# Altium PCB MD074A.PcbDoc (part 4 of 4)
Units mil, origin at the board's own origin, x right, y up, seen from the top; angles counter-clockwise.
Board outline 3224.41 x 4078.74 mil, 4 copper layers (Top Layer, Signal Layer 1, Signal Layer 2, Bottom Layer), stack 61.2 mil thick; 217 components, 121 nets, 624 pads, 901 vias.
Unrouted connection lines stored in the file: 116.
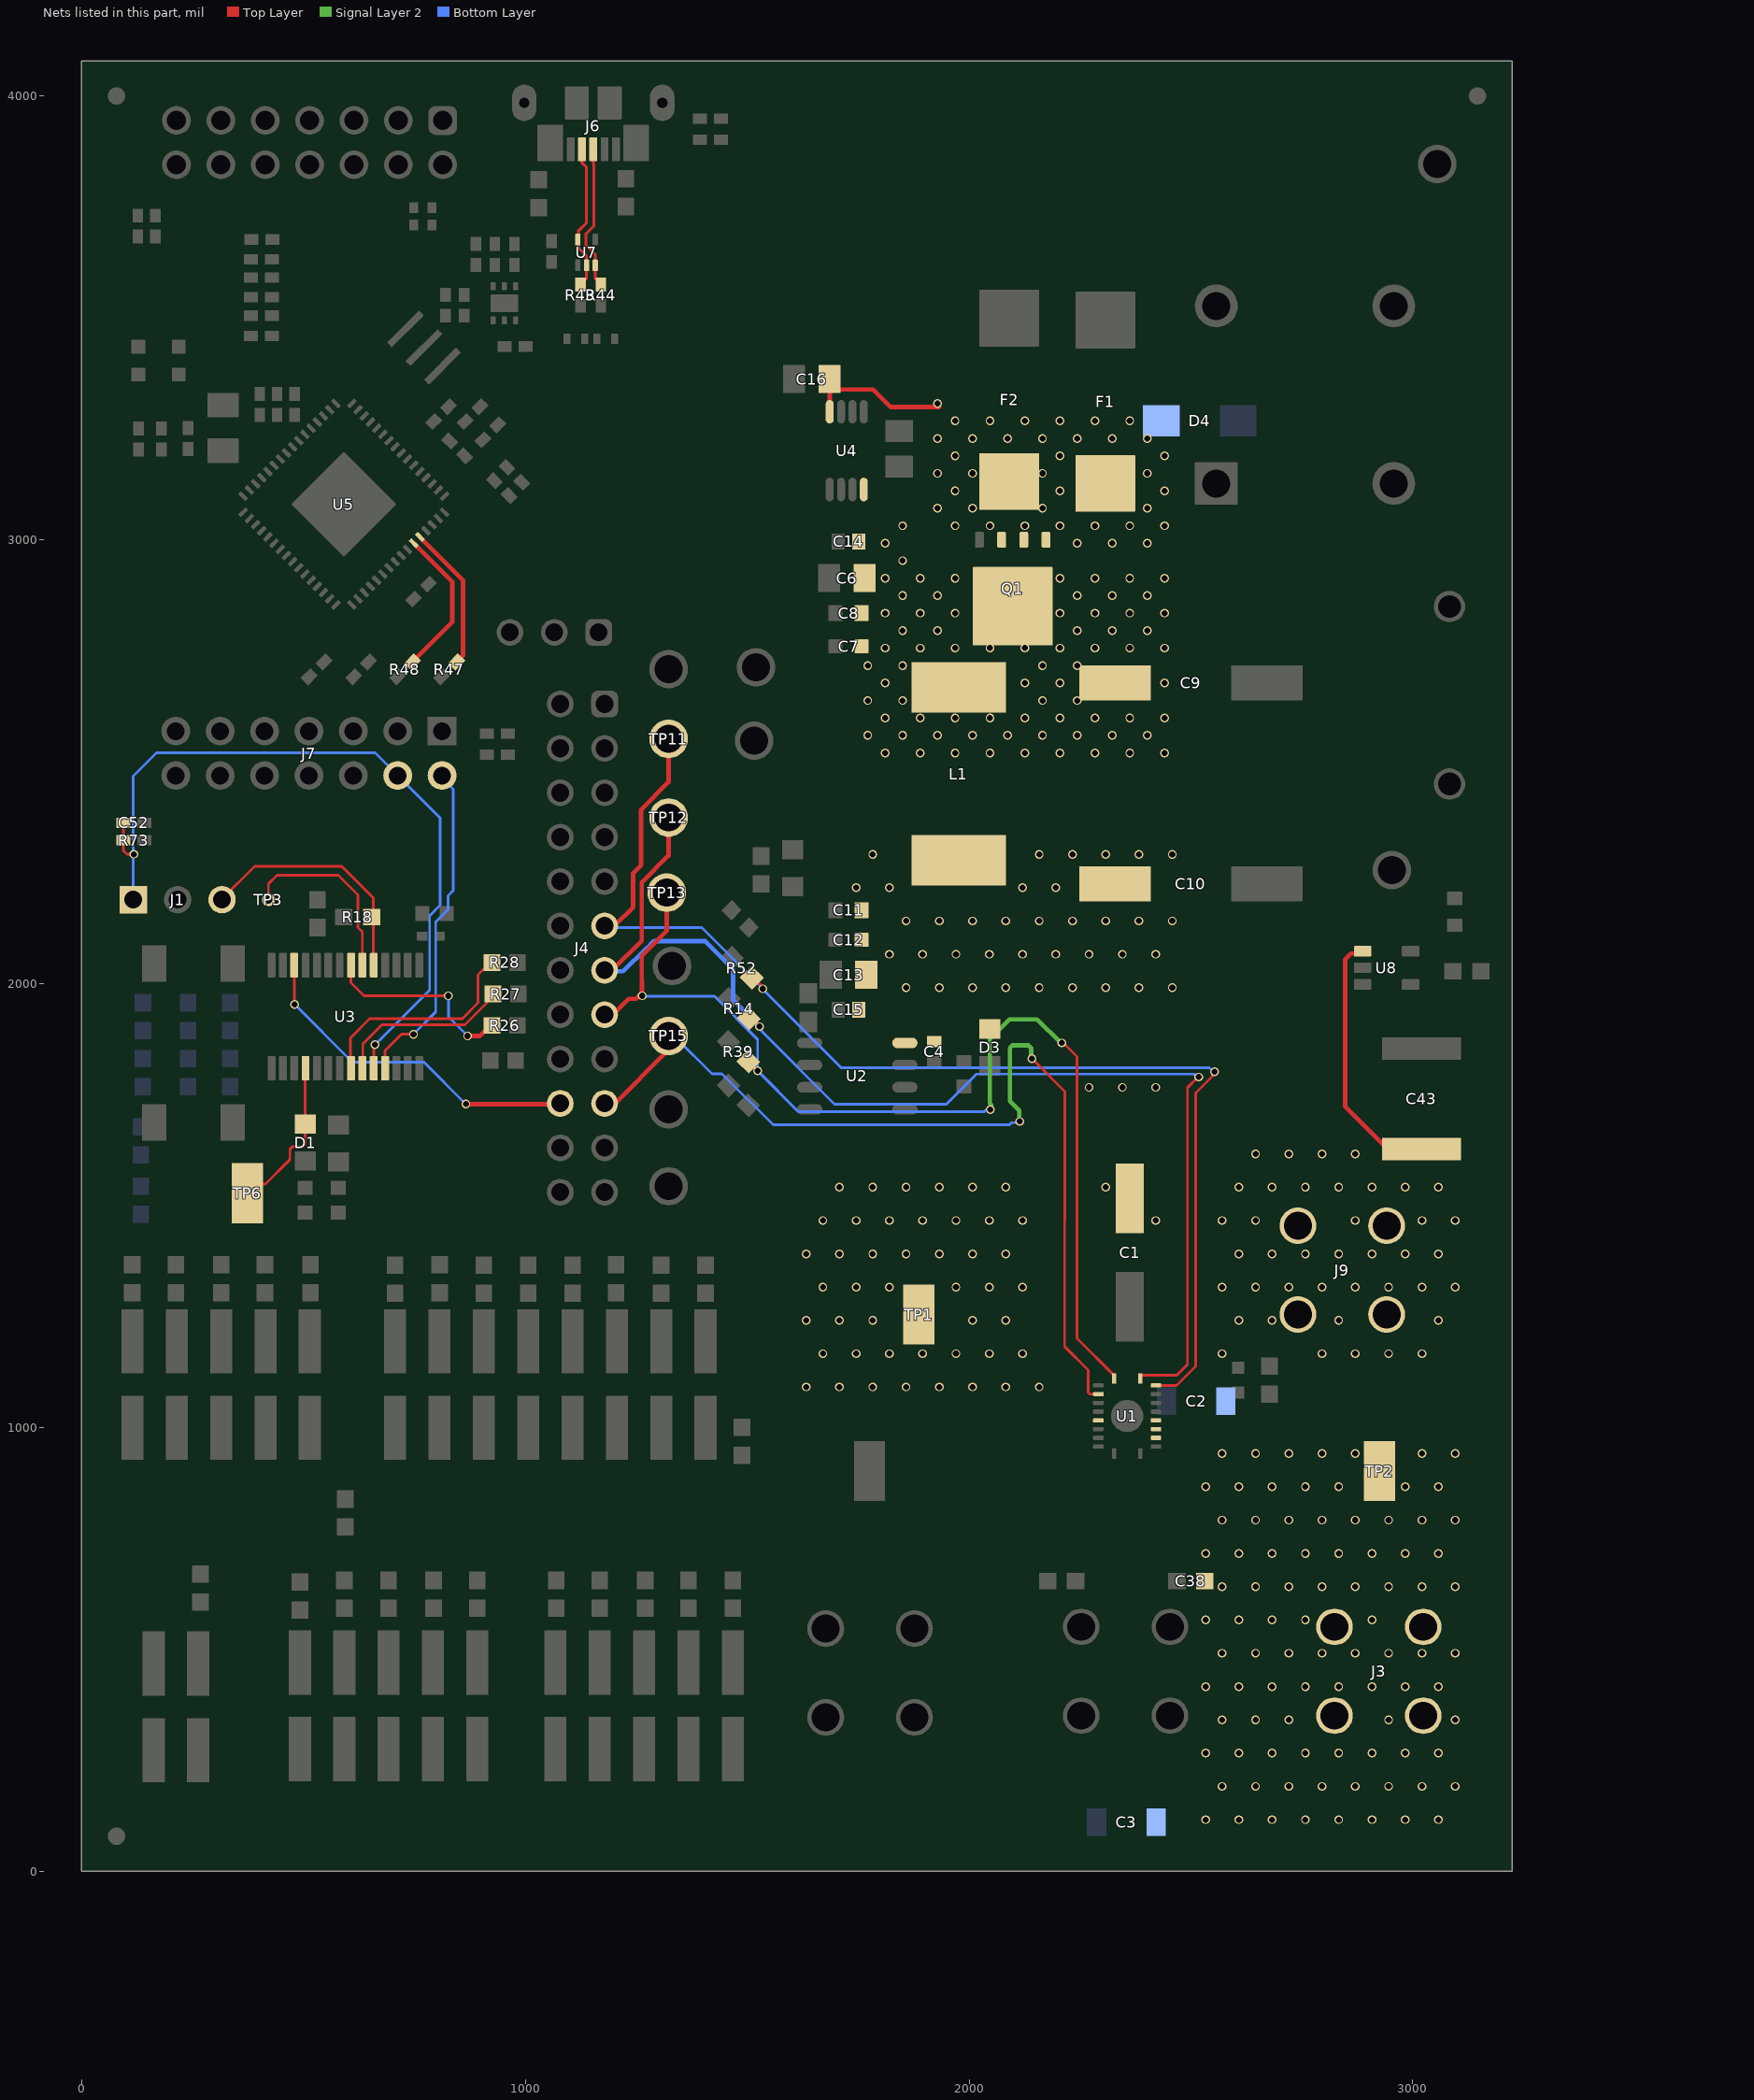
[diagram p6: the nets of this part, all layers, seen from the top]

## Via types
v1: diameter 19.68, hole 13.78, Top Layer to Bottom Layer, tented both sides, 869 vias
v2: diameter 19.68, hole 7.87, Top Layer to Bottom Layer, 14 vias
v3: diameter 19.68, hole 7.87, Top Layer to Bottom Layer, tented both sides, 9 vias
v4: diameter 19.68, hole 13.78, Top Layer to Bottom Layer, tented bottom, 5 vias
v5: diameter 24, hole 8, Top Layer to Bottom Layer, tented both sides, 4 vias

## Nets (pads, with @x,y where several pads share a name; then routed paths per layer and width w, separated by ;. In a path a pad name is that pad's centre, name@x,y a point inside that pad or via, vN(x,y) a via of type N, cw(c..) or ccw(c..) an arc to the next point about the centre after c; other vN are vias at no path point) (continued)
OUT2: C3.2 C38.2 J3.1 TP2.1 U1.13 U1.14
  other v1: 2533,116 2608,116 2683,116 2758,116 2833,116 2908,116 2983,116 3058,116 2570.5,191 2645.5,191 2720.5,191 2795.5,191 2870.5,191 2945.5,191 3020.5,191 3095.5,191 2533,266 2608,266 2608,266 2683,266 2758,266 2833,266 2908,266 2908,266 2983,266 3058,266 2570.5,341 2645.5,341 2720.5,341 2945.5,341 3095.5,341 2533,416 2608,416 2683,416 2758,416 2833,416 2908,416 2983,416 3058,416 2570.5,491 2645.5,491 2720.5,491 2795.5,491 2870.5,491 2945.5,491 3020.5,491 3095.5,491 2533,566 2608,566 2683,566 2758,566 2758,566 2908,566 2570.5,641 2645.5,641 2720.5,641 2795.5,641 2870.5,641 2945.5,641 3020.5,641 3095.5,641 2533,716 2608,716 2683,716 2758,716 2833,716 2908,716 2983,716 3058,716 2570.5,791 2645.5,791 2720.5,791 2795.5,791 2870.5,791 2945.5,791 3020.5,791 3095.5,791 2533,866 2608,866 2608,866 2683,866 2758,866 2833,866 2983,866 3058,866 2570.5,941 2645.5,941 2720.5,941 2795.5,941 2870.5,941 3020.5,941 3095.5,941
P1.4: TP3.1 U3.6 | length 426.2
  Top Layer w6: TP3.1@421.26,2188.98 421.26,2224.41 440.94,2244.09 578.74,2244.09 622.98,2199.85 622.98,2126.4 632.87,2116.51 U3.6@632.87,2041.34
P_IN: C6.2 C7.2 C8.2 C9.1 C14.1 L1.1 Q1.5 Q1.6 Q1.7 Q1.8 Q1.9@2098.43,2850.2 U4.8
  other v1: 1811.02,2519.68 1889.76,2519.68 1968.5,2519.68 2047.24,2519.68 2125.98,2519.68 2204.72,2519.68 2283.46,2519.68 2362.2,2519.68 2440.94,2519.68 1771.65,2559.06 1850.39,2559.06 1929.13,2559.06 2007.87,2559.06 2086.61,2559.06 2165.35,2559.06 2244.09,2559.06 2322.83,2559.06 2401.57,2559.06 1811.02,2598.43 1889.76,2598.43 1968.5,2598.43 2047.24,2598.43 2125.98,2598.43 2204.72,2598.43 2283.46,2598.43 2362.2,2598.43 2440.94,2598.43 1771.65,2637.8 1850.39,2637.8 2165.35,2637.8 2244.09,2637.8 1811.02,2677.17 2125.98,2677.17 2204.72,2677.17 2440.94,2677.17 1771.65,2716.54 1850.39,2716.54 2165.35,2716.54 2244.09,2716.54 1811.02,2755.91 1889.76,2755.91 1968.5,2755.91 2047.24,2755.91 2125.98,2755.91 2204.72,2755.91 2283.46,2755.91 2362.2,2755.91 2440.94,2755.91 1850.39,2795.28 1929.13,2795.28 2244.09,2795.28 2322.83,2795.28 2401.57,2795.28 1811.02,2834.65 1889.76,2834.65 1968.5,2834.65 2204.72,2834.65 2283.46,2834.65 2362.2,2834.65 2440.94,2834.65 1850.39,2874.02 1929.13,2874.02 2244.09,2874.02 2322.83,2874.02 2401.57,2874.02 1811.02,2913.39 1889.76,2913.39 1968.5,2913.39 2204.72,2913.39 2283.46,2913.39 2362.2,2913.39 2440.94,2913.39 1850.39,2952.76 1811.02,2992.13 1850.39,3031.5
PH/IN2: J4.19 TP15.1 U1.3 | length 2167.2
  Top Layer w6: v1(2141.73,1830.71) 2141.87,1830.71 2215.69,1756.89 2215.69,1469.79 2215.32,1469.42 2215.32,1182.32 2268.65,1128.98 2268.65,1078.32 2272.17,1074.8 U1.3@2291.34,1074.8
  Top Layer w10: J4.19@1196.85,1724.41 1322.83,1850.39 TP15.1@1322.83,1881.89
  Signal Layer 2 w10: v1(2113.89,1689.26) 2113.27,1689.88 2113.27,1713.82 2091.98,1735.11 2091.98,1854.9 2097.83,1860.76 2133.8,1860.76 2139.88,1854.68 2139.88,1832.56 v1(2141.73,1830.71)
  Bottom Layer w6: TP15.1@1322.63,1877.95 1339.44,1877.95 1420.55,1796.84 1443.31,1796.84 1558.53,1681.63 2091.12,1681.63 2096.14,1686.64 2111.27,1686.64 v1(2113.89,1689.26)
PH/IN2_MCU: J4.20 U3.12 | length 779
  Top Layer w6: v1@479.33,1953.74 U3.12@479.33,2041.34
  Top Layer w10: v1(866.14,1728.35) J4.20@1078.74,1728.35
  Bottom Layer w6: v1(480.32,1952.76) 610.24,1822.83 771.65,1822.83 v1(866.14,1728.35)
PUSH: J1.3 R18.1 U3.5 | length 552.5
  Top Layer w6: J1.3@314.96,2188.98 389.76,2263.78 586.61,2263.78 657.48,2192.91 657.48,2149.61 U3.5@657.48,2043.31
RST/SBWTDIO: C52.1 J1.1 J7.4 R73.1 U3.24 | length 1767.9
  Top Layer w6: C52.1@94.49,2362.2 R73.1@94.49,2322.83 94.49,2299.21 102.36,2291.34 v1(118.11,2291.34) ; U3.24@658.46,1809.06 658.46,1859.25 v1(661.42,1862.2)
  Bottom Layer w6: J1.1@116.54,2188.98 116.54,2466.93 169.29,2519.68 661.42,2519.68 808.12,2372.98 808.12,2176.46 784.31,2152.65 784.31,1985.09 v1(661.42,1862.2)
SCLK/SR: J4.15 R39.1 TP13.1 U1.1 | length 2480.1
  Top Layer w6: R39.1@1502.59,1824.19 v1(1523.62,1803.15) ; v1(2208.66,1866.14) 2212.36,1866.14 2217.72,1860.78 2217.95,1860.78 2243.44,1835.29 2243.44,1458.3 2243.06,1457.92 2243.06,1200.68 2326.77,1116.97 U1.1@2326.77,1110.24
  Top Layer w10: J4.15@1188.98,1921.26 1233.19,1965.47 1249.57,1965.47 1262.87,1978.78 1262.87,2005.06 1262.52,2005.41 1262.52,2062.72 1318.9,2119.09 TP13.1@1318.9,2204.72
  Signal Layer 2 w10: v1(2048.09,1716.22) 2049.33,1717.45 2049.33,1726.89 2046.93,1729.29 2046.93,1874.71 2091.46,1919.24 2153.36,1919.24 2206.46,1866.14 v1(2208.66,1866.14)
  Bottom Layer w6: v1(1263.78,1972.44) 1265.1,1971.12 1426.52,1971.12 1523.62,1874.02 v1(1523.62,1803.15) ; v1@1525.59,1801.18 1615.86,1710.91 2033.75,1710.91 2037.92,1715.09 2046.96,1715.09 v1(2048.09,1716.22)
SCLK_MCU: R26.2 U3.7 | length 440.6
  Top Layer w6: U3.7@607.28,2041.34 607.28,2001.82 636.66,1972.44 v1(826.77,1972.44)
  Top Layer w10: v1(870.08,1881.89) 897.64,1881.89 R26.2@921.26,1905.51
  Bottom Layer w6: v1(826.77,1972.44) 826.77,1925.2 v1(870.08,1881.89)
SDI/ITRIP: J4.13 R14.1 TP12.1 U1.20 | length 2825.6
  Top Layer w5.98: 2492.13,1157.67 2492.13,1470.38
  Top Layer w6: R14.1@1503.94,1921.26 1509.61,1921.26 v1(1527.81,1903.06) ; U1.20@2385.83,1110.24 2385.83,1115.16 2387.75,1117.08 2467.47,1117.08 2492.13,1141.73 2492.13,1157.67 ; 2492.13,1470.38 2492.13,1765.41 2515.99,1789.28 v1(2517.39,1789.28)
  Top Layer w10: J4.13@1181.1,2015.75 1229.25,2063.9 1229.88,2063.9 1262.52,2096.54 1262.52,2228.08 1322.83,2288.39 TP12.1@1322.83,2374.02
  Bottom Layer w6: v1(1527.81,1903.06) 1527.81,1899.36 1532.3,1894.87 1532.3,1892.9 1696.85,1728.35 1948.82,1728.35 2016.59,1796.12 2507.03,1796.12 2513.88,1789.28 v1(2517.39,1789.28)
  Bottom Layer w10: J4.13@1177.17,2027.56 1220.47,2027.56 1271.65,2078.74 1272.83,2078.74 1289.83,2095.74 1404.89,2095.74 1468.5,2032.13 1468.5,1962.37 v1(1527.81,1903.06)
SDI_MCU: R27.2 U3.23 | length 398.4
  Top Layer w6: U3.23@632.87,1809.06 633.86,1809.06 633.86,1863.94 677.11,1907.2 863.89,1907.2 925.2,1968.5 R27.2@925.2,1976.38
SDO/MODE: J4.11 R52.1 TP11.1 U1.19 | length 2805.7
  Top Layer w6: R52.1@1510.46,2013.16 1514.4,2013.16 v1@1537.4,1990.16 ; U1.19@2428.07,1094.49 2467.33,1094.49 2510.46,1137.62 2510.46,1753.05 2548.8,1791.39 2548.8,1793.33 2553.31,1797.83 v1(2553.31,1801.54)
  Top Layer w10: J4.11@1200.79,2129.92 1243.19,2172.32 1243.19,2248.78 1261.06,2266.65 1261.06,2391.97 1322.83,2453.74 TP11.1@1322.83,2551.18
  Bottom Layer w6: J4.11@1173.23,2125.98 1397.64,2125.98 v1(1535.43,1988.19) 1535.43,1986.45 1711.89,1809.99 2541.15,1809.99 2549.6,1801.54 v1(2553.31,1801.54)
SDO_MCU: R28.2 U3.22 | length 480.7
  Top Layer w6: U3.22@607.28,1809.06 606.3,1809.06 606.3,1877.95 649.42,1921.07 858.08,1921.07 893.7,1956.69 893.7,2019.69 R28.2@913.39,2039.37
STATUS: D1.2 TP6.1 U3.18 | length 358.5
  Top Layer w6: TP6.1@374.02,1527.56 394.82,1548.36 414.5,1548.36 469.44,1603.3 469.44,1626.55 475.81,1632.92 499.06,1632.92 503.94,1637.8 D1.2@503.94,1683.07 U3.18@503.94,1807.09
T_RST_RST: R48.1 U5.43 | length 357.6
  Top Layer w10: R48.1@745.81,2724.65 835.42,2814.26 835.42,2905.4 U5.43@748.47,2992.34 760.36,2980.45
T_TEST_TCKC: R47.1 U5.44 | length 327.9
  Top Layer w10: U5.44@762.39,3006.26 859.63,2909.02 859.63,2739.12 R47.1@845.16,2724.65
TST/SBWTCK: J7.2 U3.25 | length 751.6
  Top Layer w6: U3.25@684.05,1809.06 684.05,1848.57 721.31,1885.83 v1(748.03,1885.83)
  Bottom Layer w6: v1(748.03,1885.83) 798.18,1935.98 798.18,2138.96 825.74,2166.52 825.74,2197.56 837.88,2209.69 837.88,2437.71 J7.2@807.09,2468.5
USB_D_N: J6.2 R43.1 U7.2 U7.5 | length 330
  Top Layer w6.3: R43.1@1124.38,3575.1 1137.93,3588.65 U7.2@1137.93,3618.22 1137.93,3639.58 1119.46,3658.04 1119.46,3695.52 1137.93,3713.39 1137.93,3839.06 1127.59,3849.39 J6.2@1127.59,3879.7
USB_D_P: J6.3 R44.1 U7.3 | length 326.7
  Top Layer w6.3: J6.3@1153.18,3879.7 1153.18,3846.85 1154.23,3845.81 1154.23,3706.64 1136.19,3688.61 1136.19,3664.36 1157.61,3642.94 U7.3@1157.61,3618.22 1157.61,3587.9 R44.1@1170.41,3575.1
VBAT: C16.1 D4.2 F1.1 F2.1 Q1.1 Q1.2 Q1.3 U4.4 | length 351.1
  Top Layer w6: C16.1@1686.02,3355.31 C16.1@1688.98,3358.27
  Top Layer w10: C16.1@1685.67,3362.2 1709.29,3338.58 1783.46,3338.58 1822.83,3299.21 v1@1933.07,3299.21 ; U4.4@1686.02,3288.39 C16.1@1686.02,3361.22 ; F2.1@2066.52,3126.4 F2.1@2066.93,3125.98
  other v1: 2244.09,2992.13 2322.83,2992.13 2401.57,2992.13 1968.5,3031.5 2047.24,3031.5 2125.98,3031.5 2204.72,3031.5 2283.46,3031.5 2362.2,3031.5 2440.94,3031.5 1929.13,3070.87 2007.87,3070.87 2165.35,3070.87 2401.57,3070.87 1968.5,3110.24 2204.72,3110.24 2440.94,3110.24 1929.13,3149.61 2007.87,3149.61 2165.35,3149.61 2401.57,3149.61 1968.5,3188.98 2204.72,3188.98 2440.94,3188.98 1929.13,3228.35 2007.87,3228.35 2086.61,3228.35 2165.35,3228.35 2244.09,3228.35 2322.83,3228.35 2401.57,3228.35 1968.5,3267.72 2047.24,3267.72 2125.98,3267.72 2204.72,3267.72 2283.46,3267.72 2362.2,3267.72 1929.13,3307.09
VM: C1.1 C2.1 C4.1 C10.1 C11.2 C12.2 C13.2 C15.1 C43.1 D3.2 J9.1 L1.2 TP1.1 U1.6 U1.15 U2.8 U8.1 | length 504.6
  Top Layer w10: U8.1@2886.81,2072.83 2881.44,2067.47 2860.65,2067.47 2847.44,2054.26 2847.44,1723.43 C43.1@2937.01,1633.86
  other v1: 1633,1091 1708,1091 1783,1091 1858,1091 1933,1091 2008,1091 2083,1091 2158,1091 1670.5,1166 1745.5,1166 1820.5,1166 1895.5,1166 1970.5,1166 2045.5,1166 2120.5,1166 2570.5,1166 2795.5,1166 2870.5,1166 2945.5,1166 3020.5,1166 1633,1241 1708,1241 1783,1241 2008,1241 2083,1241 2608,1241 2683,1241 2833,1241 3058,1241 1670.5,1316 1745.5,1316 1820.5,1316 1970.5,1316 2045.5,1316 2120.5,1316 2570.5,1316 2645.5,1316 2720.5,1316 2795.5,1316 2870.5,1316 2945.5,1316 3020.5,1316 3095.5,1316 1633,1391 1708,1391 1783,1391 1858,1391 1933,1391 2008,1391 2083,1391 2608,1391 2683,1391 2758,1391 2833,1391 2908,1391 2983,1391 3058,1391 1670.5,1466 1745.5,1466 1820.5,1466 1895.5,1466 1970.5,1466 2045.5,1466 2120.5,1466 2420.5,1466 2570.5,1466 2645.5,1466 2870.5,1466 3020.5,1466 3095.5,1466 1708,1541 1783,1541 1858,1541 1933,1541 2008,1541 2083,1541 2308,1541 2608,1541 2683,1541 2758,1541 2833,1541 2908,1541 2983,1541 3058,1541 2645.5,1616 2720.5,1616 2795.5,1616 2870.5,1616 2270.5,1766 2345.5,1766 2420.5,1766 1858,1991 1933,1991 2008,1991 2083,1991 2158,1991 2233,1991 2308,1991 2383,1991 2458,1991 1820.5,2066 1895.5,2066 1970.5,2066 2045.5,2066 2120.5,2066 2195.5,2066 2270.5,2066 2345.5,2066 2420.5,2066 1858,2141 1933,2141 2008,2141 2083,2141 2158,2141 2233,2141 2308,2141 2383,2141 2458,2141 1745.5,2216 1820.5,2216 2120.5,2216 2195.5,2216 1783,2291 2158,2291 2233,2291 2308,2291 2383,2291 2458,2291
pads on no net: FID1.1 FID2.1 FID3.1 H1.0 H2.0 H3.0 H4.0 J4.2 J4.3 J4.4 J5.6 J5.10 J5.12 J5.13 J5.14 J6.4 J7.11 J7.12 J13.3 J16.3 LBL1.0 Q1.9@2041.34,2834.65 Q1.9@2041.34,2904.72 Q1.9@2098.43,2834.65 Q1.9@2098.43,2868.11 Q1.9@2098.43,2904.72 Q1.9@2155.51,2834.65 Q1.9@2155.51,2904.72 S1.2 SH-J1.0 SH-J2.0 SH-J3.0 SH-J4.0 SH-J5.0 SH-J6.0 SH-J7.0 SH-J8.0 SH-J9.0 SH-J10.0 SH-J11.0 SH-J12.0 SH-J13.0 SH-J14.0 SH-J15.0 SH-J16.0 SH-J17.0 SH-J19.0 SH-J20.0 SH-J21.0 SH-J22.0 SH-J23.0 U3.11 U3.15 U3.19 U3.20 U3.21 U4.3 U4.5 U5.3 U5.4 U5.5 U5.6 U5.7 U5.8 U5.10 U5.12 U5.13 U5.18 U5.19 U5.22 U5.23 U5.24 U5.25 U5.26 U5.27 U5.28 U5.29 U5.30 U5.31 U5.32 U5.33 U5.34 U5.35 U5.36 U5.41 U5.42 U5.45 U5.46 U5.47 U5.48 U6.7@935.1,3532.82 U6.7@970.53,3532.82 U8.2

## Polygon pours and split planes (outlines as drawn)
VM on Top Layer "TOP_LAYER_NONET_P-001" (solid, pour order 278): 2165.35,1657.48 1570.87,1657.48 1570.87,1009.84 3153.54,1009.84 3153.54,1661.42 2559.06,1661.42 2559.06,1141.73 2448.82,1031.5 2275.59,1031.5 2165.35,1141.73
GND on Top Layer "TOP_LAYER_GND_P283" (solid, remove dead copper, pour order 283): 3.1,-0.22 3227.51,-0.22 3227.51,4078.52 3.1,4078.52
OUT2 on Top Layer "TOP_LAYER_OUT2_P270" (solid, pour order 270): 2358.27,1001.97 2358.27,940.94 2503.94,940.94 2503.94,78.74 3149.61,78.74 3149.61,1001.97
VM on Top Layer "TOP_LAYER_VM_P275" (solid, pour order 275): 2240.16,1397.64 2488.19,1397.64 2488.19,2381.89 1732.28,2381.89 1732.28,1854.33 2240.16,1854.33
GND on Top Layer "TOP_LAYER_GND_P272" (solid, pour order 272): 2240.16,1397.64 2476.38,1397.64 2476.38,1090.55 2236.22,1090.55
OUT1 on Top Layer "TOP_LAYER_OUT1_P281" (solid, pour order 281): 2362.2,1001.97 2362.2,940.94 2216.54,940.94 2216.54,78.74 1570.87,78.74 1570.87,1001.97
VM on Top Layer "TOP_LAYER_VM_P271" (solid, pour order 271): 2311.02,1027.56 2311.02,1078.74 2409.45,1078.74 2409.45,1027.56
EZFET_USB_Shield on Top Layer "TOP_LAYER_EZFET_USB_SHIELD_P273" (solid, remove dead copper, pour order 273): 936.96,4067.41 1413.03,4067.41 1413.03,3859.53 936.96,3859.53
VBAT on Top Layer "TOP_LAYER_VBAT_P274" (solid, pour order 274): 2476.38,3322.83 2476.38,2964.57 1901.57,2964.57 1901.57,3322.83
P_IN on Top Layer "TOP_LAYER_P_IN_P276" (solid, pour order 276): 2488.19,2389.76 2488.19,3141.73 1736.22,3141.73 1736.22,2389.76
NetF1_2 on Top Layer "TOP_LAYER_NETF1_2_P277" (solid, pour order 277): 1897.64,3326.77 3102.36,3326.77 3102.36,3913.39 1897.64,3913.39
VM on Bottom Layer "BOTTOM_LAYER_VM_P303" (solid, pour order 303): 1574.8,1007.87 3149.61,1007.87 3149.61,1655.51 1574.8,1655.51
GND on Bottom Layer "BOTTOM_LAYER_GND_P304" (solid, remove dead copper, pour order 304): 0,0 3224.41,0 3224.41,4078.74 0,4078.74
EZFET_USB_Shield on Bottom Layer "BOTTOM_LAYER_EZFET_USB_SHIELD_P296" (solid, remove dead copper, pour order 296): 936.96,4067.41 1413.03,4067.41 1413.03,3859.53 936.96,3859.53
GND on Bottom Layer "BOTTOM_LAYER_GND_P297" (solid, pour order 297): 2496.06,1401.57 2240.16,1401.57 2232.28,1409.45 2212.6,1389.76 2212.6,881.89 2496.06,881.89
VBAT on Bottom Layer "BOTTOM_LAYER_VBAT_P298" (solid, pour order 298): 2476.38,3322.83 2476.38,2964.57 1901.57,2964.57 1901.57,3322.83
P_IN on Bottom Layer "BOTTOM_LAYER_P_IN_P299" (solid, pour order 299): 2488.19,2373.23 2488.19,3141.73 1736.22,3141.73 1736.22,2373.23
OUT1 on Bottom Layer "TOP_LAYER_NONET_P-001" (solid, pour order 300): 2318.9,80.71 2318.9,141.73 2204.72,141.73 2204.72,960.63 2358.27,960.63 2358.27,1000 1574.8,1000 1574.8,80.71
OUT2 on Bottom Layer "TOP_LAYER_NONET_P-001" (solid, pour order 301): 2389.76,80.71 3149.61,80.71 3149.61,1000 2358.27,1000 2358.27,960.63 2507.87,960.63 2507.87,141.73 2389.76,141.73
NetF1_2 on Bottom Layer "BOTTOM_LAYER_NETF1_2_P302" (solid, pour order 302): 1897.64,3326.77 3102.36,3326.77 3102.36,3913.39 1897.64,3913.39
VM on Signal Layer 2 "SIGNAL_LAYER_2_VM_P294" (solid, pour order 294): 3148.7,1652.85 3148.7,78.04 1573.9,78.04 1573.9,1652.85
VM on Signal Layer 2 "SIGNAL_LAYER_2_VM_P285" (solid, pour order 285): 2165.35,1692.91 2165.35,1629.92 2559.06,1629.92 2559.06,1692.91
GND on Signal Layer 2 "s" (solid, remove dead copper, pour order 295): 27.9,-16.61 3252.31,-16.61 3252.31,4062.13 27.9,4062.13
VM on Signal Layer 2 "SIGNAL_LAYER_2_VM_P290" (solid, pour order 290): 1618.11,1665.35 2559.05,1665.35 2559.06,2366.14 1618.11,2366.14
NetF1_2 on Signal Layer 2 "SIGNAL_LAYER_2_NETF1_2_P291" (solid, pour order 291): 1897.64,3326.77 3102.36,3326.77 3102.36,3913.39 1897.64,3913.39
EZFET_VCC on Signal Layer 2 "SIGNAL_LAYER_2_EZFET_VCC_P293" (solid, remove dead copper, pour order 293): 8.99,2518.8 937.86,2518.8 937.86,3524.84 792.38,3524.84 792.27,3524.96 792.27,4067.37 10.03,4067.37 8.99,4068.41
EZFET_VBUS on Signal Layer 2 "SIGNAL_LAYER_2_EZFET_VBUS_P287" (solid, remove dead copper, pour order 287): 792.27,4067.37 1412.99,4067.37 1413.03,4067.41 1416.99,4063.45 1416.99,3519.39 793.66,3519.39
3V3_MCU on Signal Layer 2 "SIGNAL_LAYER_2_3V3_MCU_P292" (solid, pour order 292): 0,2503.94 952.76,2503.94 952.76,2665.35 1165.35,2665.35 1165.35,1452.76 0,1452.76
3V3 on Signal Layer 2 "SIGNAL_LAYER_2_3V3_P288" (solid, pour order 288): 1251.97,2574.8 1259.84,2566.93 1614.17,2566.93 1614.17,1448.82 1259.84,1448.82
VBAT on Signal Layer 2 "SIGNAL_LAYER_2_VBAT_P286" (solid, pour order 286): 2476.38,3322.83 2476.38,2964.57 1901.57,2964.57 1901.57,3322.83
P_IN on Signal Layer 2 "SIGNAL_LAYER_2_P_IN_P289" (solid, pour order 289): 2488.19,2373.23 2488.19,3141.73 1736.22,3141.73 1736.22,2373.23
GND on Signal Layer 1 "TOP_LAYER_NONET_P-001" (solid, pour order 282): 1574.8,1653.54 3149.61,1653.54 3149.61,78.74 1574.8,78.74
GND on Signal Layer 1 "SIGNAL_LAYER_1_GND_P284" (solid, pour order 284): 7.87,4082.68 3228.35,4082.68 3224.41,4078.74 3224.41,1661.42 1555.12,1661.42 1555.12,0 -12.02,0
GND on Signal Layer 1 "SIGNAL_LAYER_1_GND_P280" (solid, pour order 280): 2165.35,1614.17 2165.35,1692.91 2559.06,1692.91 2559.06,1614.17

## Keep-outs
Keep-Out Layer:
  text ".Layer_Name" at 577,-858.49 h25

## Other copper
Top Layer:
  pour cut-out: 1570.87,78.74 3224.41,78.74 3224.41,0 1570.87,0
  pour cut-out: 3153.54,1657.48 3224.41,1657.48 3224.41,0 3153.54,0
  text ".Layer_Name" at 577,-858.49 h25
Bottom Layer:
  pour cut-out: 3224.41,1653.54 3161.42,1653.54 3161.42,0 3220.47,0 3224.41,-7.87
  pour cut-out: 1574.8,78.74 3224.41,78.74 3224.41,0 1574.8,0
  text ".Layer_Name" at 577,-858.49 h25

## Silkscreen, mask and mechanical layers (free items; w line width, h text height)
Top Overlay:
  lines w3.94: 3149.61,78.74 3149.61,78.74
  lines w7.87: 1574.8,78.74 1574.8,1653.54 3149.61,1653.54 3149.61,78.74 1574.8,78.74
  lines w10: 779.53,4003.94 870.08,4003.94 870.08,3909.45
  text "For EZFET-LITE Flashing Only" at 185.04,4019.69 h25
  text "1" at 885.83,3992.13 h25
  text "+BAT" at 2822.83,3826.77 h35
  text "'.PRJ_Number'.PCB_Rev" at 1338.58,3669.29 h35
  text "PWR" at 87.05,3315.24 h25
  text "MODE" at 180.25,3315.26 h25
  text "3V3_MCU" at 1062.99,2850.39 h25 r45
  text "3V3" at 1169.29,2850.39 h25 r45
  text "GND" at 2909.45,2814.96 h35
  text "GND" at 1118.11,2685.04 h25
  text "nSLEEP" at 884.63,2413.39 h25
  text "GND" at 188.12,2405.81 h25 r270
  text "3V3" at 389.76,2405.81 h25 r270
  text ">>RX" at 492.13,2405.81 h25 r270
  text "<<TX" at 590.55,2405.81 h25 r270
  text "TDIO" at 688.98,2405.81 h25 r270
  text "TCK" at 791.34,2405.81 h25 r270
  text "nFAULT" at 1476.38,2350.39 h25
  text "VDD" at 2873.14,2337.71 h25
  text "IPROPI" at 897.13,2322.83 h25
  text "nFAULT" at 884.63,2224.41 h25
  text "SDO/MODE" at 834.65,2118.11 h25
  text "RST" at 86.61,2102.36 h25
  text "PUSH" at 287.4,2102.36 h25
  text "SDI/ITRIP" at 811.02,1992.13 h25
  text "VM" at 2007.87,1925.2 h25
  text "SCLK/SR" at 846.46,1921.26 h25
  text "nSCS/DIAG" at 807.09,1846.46 h25
  text "PH/IN2" at 888.79,1720.47 h25
  text "EN/IN1" at 897.13,1622.05 h25
  text "3V3" at 657.48,1598.43 h25 r90
  text "DRV8242 QFN" at 1598.43,1596.68 h35
  text "Status" at 460.63,1570.87 h25 r90
  text "40mm x 40mm" at 1598.43,1532.86 h35
  text "DRVOFF" at 884.63,1519.68 h25
  text "4 layers" at 1598.43,1457.37 h35
  text "2oz copper" at 1598.43,1381.89 h35
  text "VM" at 2586.61,1330.71 h35
  text "VM" at 1940.94,1287.4 h35 r270
  text "OUT1" at 1834.65,972.44 h35 r270
  text "OUT2" at 2988.19,960.63 h35 r270
  text "680" at 1381.89,834.65 h25 r45
  text "6.8k" at 779.53,830.71 h25 r45
  text "2.2k" at 1078.74,830.71 h25 r45
  text "1.0k" at 1271.65,830.71 h25 r45
  text "LVL4" at 169.29,826.77 h25 r45
  text "LVL3" at 271.65,826.77 h25 r45
  text "8.2k" at 688.98,826.77 h25 r45
  text "3.3k" at 976.38,826.77 h25 r45
  text "1.5k" at 1173.23,826.77 h25 r45
  text "LVL5" at 70.87,822.83 h25 r45
  text "LVL2" at 370.08,822.83 h25 r45
  text "LVL1" at 468.5,822.83 h25 r45
  text "4.7k" at 877.95,822.83 h25 r45
  text "ITRIP" at 244.09,751.97 h35
  text "IPROPI" at 980,740 h35
  text "GND" at 2303.15,696.85 h35
  text "OUT1" at 1720.47,661.42 h35
  text "OUT2" at 2866.14,649.61 h35
  text "LVL4" at 551.18,106.3 h25 r45
  text "LVL3" at 653.54,106.3 h25 r45
  text "LVL4" at 1129.92,106.3 h25 r45
  text "LVL3" at 1232.28,106.3 h25 r45
  text "LVL2" at 169.29,102.36 h25 r45
  text "LVL1" at 267.72,102.36 h25 r45
  text "LVL5" at 452.76,102.36 h25 r45
  text "LVL2" at 751.97,102.36 h25 r45
  text "LVL1" at 850.39,102.36 h25 r45
  text "LVL5" at 1031.5,102.36 h25 r45
  text "LVL2" at 1330.71,102.36 h25 r45
  text "LVL1" at 1429.13,102.36 h25 r45
  text "MODE" at 118.11,39.37 h35
  text "SLEW RATE" at 507.87,39.37 h35
  text "DIAG" at 1188.98,39.37 h35
  text ".Layer_Name" at 577,-858.49 h25
Bottom Overlay:
  text "ID1" at 173.23,2007.87 h25
  text "ID2" at 267.72,2007.87 h25
  text "ID3" at 366.14,2007.87 h25
  text "0" at 405.51,1909.45 h25
  text "1" at 405.51,1779.53 h25
  text "ID0" at 264.65,1558.18 h25
  text ".Layer_Name" at 577,-858.49 h25
Top Paste:
  text ".Layer_Name" at 577,-858.49 h25
Bottom Paste:
  text ".Layer_Name" at 577,-858.49 h25
Top Solder:
  text ".Layer_Name" at 577,-858.49 h25
  text ".Layer_Name" at 577,-858.49 h25
Bottom Solder:
  text ".Layer_Name" at 577,-858.49 h25
Drill Guide:
  text ".Layer_Name" at 577,-858.49 h25
M1 Board Outline:
  lines w7.87: 3216.54,0 3216.54,4073.9
  lines w10: 3216.54,0 0,0 0,4076.1 3216.54,4073.9
  text ".Layer_Name" at 577,-858.49 h25
M2 Board Dimensions:
  rectangle: 0,-275 125,-150
  rectangle: 125,-400 500,-275
  lines w7: 0,-275 1000,-275 ; 125,-400 125,-150 ; 250,-400 250,-150 ; 500,-400 500,-150 ; 750,-400 750,-150 ; 0,-400 1000,-400 1000,-150 0,-150 0,-400
  text ".Layer_Name" at 577,-858.49 h25
M3 3D STEP Top:
  text ".Layer_Name" at 577,-858.49 h25
M4 3D STEP Bottom:
  text ".Layer_Name" at 577,-858.49 h25
M5 Assembly Top:
  lines w10: -292,-930.17 6308,-930.17 ; -292,-726.83 6310,-726.83 ; -292,-523.5 -292,-1133.5 3713,-1133.5 6310,-1133.5 6310,-523.5 -291.5,-523.5 -291.5,-1133.5 1284,-1133.5 ; 2173,-1133.5 2173,-523.5 ; 3440,-726.83 3440,-523.5 ; 4280,-726.83 4280,-523.5 ; 4902,-1140 4902,-937.17
  text "COMPONENTS MARKED 'DNP' SHOULD NOT BE POPULATED." at 1153.5,-318.5 h25
  text "ASSEMBLY VARIANT:" at 1153,-434 h25
  text ".VariantName" at 2189,-434 h25
  text "PCB VIEWED FROM TOP SIDE" at -228.5,-655.67 h25
  text "BOARD #:" at 2248,-655.67 h25
  text ".PRJ_Number" at 2793.5,-655.67 h25
  text "REV:" at 3638,-655.67 h25
  text ".PCB_Rev" at 3929.5,-655.67 h25
  text "SVN REV:" at 4476,-655.67 h25
  text ".VersionControl_RevNumber" at 4982,-655.67 h25
  text "TID #:" at 2248,-859 h25
  text ".TID" at 2793.5,-859 h25
  text "PLOT NAME =" at -228.5,-1064.34 h25
  text ".plot_File_Name" at 577,-1064.34 h25
  text "GENERATED    :" at 2250,-1064.34 h25
  text ".Print_Date" at 3119.5,-1064.34 h25
  text ".Print_Time" at 3848.5,-1064.34 h25
  text "TEXAS INSTRUMENTS" at 5113,-1064.34 h25
M6 Assembly Bottom:
  lines w10: -292.5,-727.33 6309.5,-727.33 ; -290.5,-930.67 6309.5,-930.67 ; 1115.5,-1140.5 1115.5,-937.67 ; 1737.5,-727.33 1737.5,-524 ; 2577.5,-727.33 2577.5,-524 ; 3844.5,-1134 3844.5,-524 ; 4733.5,-1134 6309,-1134 6309,-524 -292.5,-524 -292.5,-1134 2304.5,-1134 6309.5,-1134 6309.5,-524
  text "COMPONENTS MARKED 'DNP' SHOULD NOT BE POPULATED." at 6102,-318 h25
  text ".VariantName" at 5058,-434 h25
  text "ASSEMBLY VARIANT:" at 6097,-434 h25
  text ".VersionControl_RevNumber" at 1035.5,-656.17 h25
  text "SVN REV:" at 1541.5,-656.17 h25
  text ".PCB_Rev" at 2088,-656.17 h25
  text "REV:" at 2379.5,-656.17 h25
  text ".PRJ_Number" at 3224,-656.17 h25
  text "BOARD #:" at 3769.5,-656.17 h25
  text "PCB VIEWED FROM BOTTOM SIDE" at 6246,-656.17 h25
  text ".TID" at 3224,-859.5 h25
  text "TID #:" at 3769.5,-859.5 h25
  text "TEXAS INSTRUMENTS" at 904.5,-1064.84 h25
  text ".Print_Time" at 2169,-1064.84 h25
  text ".Print_Date" at 2898,-1064.84 h25
  text "GENERATED    :" at 3767.5,-1064.84 h25
  text ".plot_File_Name" at 5440.5,-1064.84 h25
  text "PLOT NAME =" at 6246,-1064.84 h25
M9 Title Sheet:
  drawing of 57 lines, arcs and shapes, not listed
  text "1" at 739.84,8036.5 h25
  text "2" at 3235.5,8036.5 h25
  text "3" at 5724.84,8036.5 h25
  text "4" at 8231.51,8036.5 h25
  text "5" at 10730.5,8036.5 h25
  text "6" at 13235.5,8036.5 h25
  text "A" at -416.5,6893.5 h25
  text "A" at 14383.5,6893.5 h25
  text "B" at -416.5,4513.5 h25
  text "B" at 14383.5,4513.5 h25
  text "C" at -416.5,2138.5 h25
  text "C" at 14383.5,2138.5 h25
  text "PROJECT TITLE:" at 11343.5,277.5 h25
  text ".PRJ_Title" at 11393.5,144.17 h25
  text "DESIGNED FOR:" at 11343.5,-23.5 h25
  text ".PRJ_Customer" at 11393.5,-163.5 h25
  text "D" at -416.5,-231.5 h25
  text "D" at 14383.5,-231.5 h25
  text "FILE NAME:" at 11343.5,-323.5 h25
  text ".PCB_File_Name_No_Path" at 11393.5,-443.5 h25
  text "Texas Instruments (TI) and/or its licensors do not warrant the accuracy or completeness of this specification" at 6374,-605.34 h25
  text "ENGINEER:" at 11343.5,-613.5 h25
  text "LAYOUT BY:" at 12848.5,-613.5 h25
  text "or any information contained therein. TI and/or its licensors do not warrant that this design will meet" at 6329.01,-718 h25
  text ".PRJ_Engineer" at 11393.5,-768.49 h25
  text ".PCB_Layout" at 12899,-768.49 h25
  text "the specifications, will be suitable for your application or fit for any particular purpose, or will operate in" at 6329.01,-830.67 h25
  text ".Layer_Name" at 577,-858.49 h25
  text "ALTIUM DESIGNER VERSION:" at 12848.5,-923.5 h25
  text "an implementation. TI and/or its licensors do not warrant that the design is production worthy. You should" at 6329.01,-943.33 h25
  text "completely validate and test your design implementation to confirm the system functionality for your application." at 6374,-1056 h25
  text ".print_Scale" at 11393.5,-1056.83 h25
  text ".Application_BuildNumber" at 12899,-1056.83 h25
  text "1" at 739.84,-1263.5 h25
  text "2" at 3235.5,-1263.5 h25
  text "3" at 5724.84,-1263.5 h25
  text "4" at 8231.51,-1263.5 h25
  text "5" at 10730.5,-1263.5 h25
  text "6" at 13235.5,-1263.5 h25
M10 Fab Notes:
  drawing of 189 lines, arcs and shapes, not listed
  text "DESIGN INFORMATION" at 12382.02,6356.17 h25
  text "MIN. TRACK WIDTH:" at 11737.46,6224.05 h25
  text "8" at 12833.7,6224.05 h25
  text "MIL" at 12988.46,6224.05 h25
  text "MIN. CLEARANCE:" at 11737.46,6099.92 h25
  text "0.2" at 12773.7,6099.93 h25
  text "mm" at 12988.46,6099.92 h25
  text "MIN. VIA PAD SIZE:" at 11737.46,5975.8 h25
  text "24" at 12803.71,5975.8 h25
  text "MIL" at 12988.46,5975.8 h25
  text "0.05mm (2MIL)" at 12432.46,5845.9 h25
  text "MINIMUM ANNULAR RING" at 11408.23,5837.67 h25
  text "EXTERNAL" at 13140.46,5837.67 h25
  text "PER" at 11608.23,5727.55 h25
  text "IPC-D-275 CLASS 2 LEVEL C" at 11828.23,5727.54 h25
  text "MIL, HOLES" at 13316.46,5627.07 h25
  text "+/-" at 12924,5618.48 h25
  text "+/-" at 13778,5618.48 h25
  text "REGISTRATION TOLERANCES:" at 11408.23,5617.42 h25
  text "METAL" at 12608,5617.42 h25
  text "5" at 13184.2,5617.42 h25
  text "3" at 14017.2,5617.42 h25
  text "MIL" at 14133.46,5617.42 h25
  text "HOLE SIZE TOLERANCE (UNLESS OTHERWISE SPECIFIED):" at 11408.23,5519.1 h25
  text "+/-" at 13778,5516.23 h25
  text "3" at 14017.2,5515.17 h25
  text "MIL" at 14133.46,5515.17 h25
  text "MATERIAL:" at 11333.46,5377.52 h25
  text "FR-4 High Tg" at 12319.9,5249 h25
  text "X" at 12175.46,5241.01 h25
  text "FR-408" at 11754.46,5236.49 h25
  text "OTHER" at 13242.46,5236.49 h25
  text "62 MIL (1.6mm) +/-10%" at 12074.56,5093.46 h25
  text "X" at 11954.46,5091.01 h25
  text "THICKNESS:" at 11408.23,5085.24 h25
  text "OTHER" at 13359.46,5085.24 h25
  text "TOLERANCE:" at 11408.23,4946.92 h25
  text "X" at 12256.46,4946.92 h25
  text "ANSI IPC-6012 TYPE 3 CLASS 2" at 12434.48,4946.92 h25
  text "OTHER +/-" at 12434.46,4802.73 h25
  text "BOW & TWIST:" at 11408.23,4657.54 h25
  text "X" at 12256.46,4657.54 h25
  text "ANSI IPC-6012 TYPE 3 CLASS 2" at 12434.48,4657.54 h25
  text "OTHER +/-" at 12434.46,4510.85 h25
  text "DRILLING:" at 11333.46,4380.23 h25
  text "NC_DRILL FILES" at 13094.46,4275.04 h25
  text "REFERENCE:" at 11408.23,4271.1 h25
  text "X" at 12065.46,4271.01 h25
  text "AS SHOWN" at 12243.46,4271.1 h25
  text "X" at 12966.46,4271.1 h25
  text "OTHER" at 13392.46,4128.85 h25
  text "PTH COPPER THICKNESS:" at 11407.91,4125.32 h25
  text "X" at 12547.14,4125.32 h25
  text "20-30 um" at 12675.14,4125.32 h25
  text "BOARD FINISH:" at 11333.46,3977.73 h25
  text "SILKSCREEN:" at 11488.68,3867.6 h25
  text "X" at 12446.46,3867.6 h25
  text "TOP" at 12563.46,3867.6 h25
  text "X" at 12956.46,3867.6 h25
  text "BOTTOM" at 13074.46,3867.6 h25
  text "SILKSCREEN COLOR:" at 11488.68,3712.41 h25
  text "X" at 12445.46,3712.41 h25
  text "WHITE" at 12563.46,3712.41 h25
  text "OTHER" at 13074.46,3712.41 h25
  text "X" at 12576.46,3568.96 h25
  text "GREEN" at 12694.46,3568.96 h25
  text "OTHER" at 13312.46,3568.96 h25
  text "SOLDER RESIST COLOR:" at 11488.68,3562.1 h25
  text "X" at 12576.46,3414.71 h25
  text "MATTE" at 12694.46,3414.71 h25
  text "SEMI-GLOSS" at 13312,3414.07 h25
  text "IMMERSION GOLD (ENIG)" at 12394.46,3241.94 h25
  text "ENEPIG" at 13732,3234.72 h25
  text "SURFACE FINISH:" at 11333.46,3233.72 h25
  text "X" at 12216.46,3233.72 h25
  text "IMM. TIN/SILVER OR EQUIV" at 11663,3096.4 h25
  text "OTHER" at 13094.46,3092.47 h25
  text "ARRAY/PANEL:" at 11333.46,2937.09 h25
  text "CUT AND TRIM PER M1 BOARD OUTLINE" at 12394.46,2928.87 h25
  text "N.C. ROUTE" at 12394.46,2792.9 h25
  text "X" at 13082.46,2792.9 h25
  text "V. SCORE" at 13260.46,2792.9 h25
  text "CERTIFICATION:" at 11333.46,2663.77 h25
  text "MATERIALS AND WORKMANSHIP FOR ALL PCBS" at 12058.46,2663.77 h25
  text "TO MEET OR EXCEED THE REQUIREMENTS OF:" at 12058.46,2569.71 h25
  text "X" at 11695.97,2441.08 h25
  text "ANSI IPC-A-600F CLASS ->" at 11823.96,2441.08 h25
  text "X" at 13471.97,2441.08 h25
  text "2" at 13581.96,2441.08 h25
  text "1" at 13266.96,2439.58 h25
  text "3" at 13935.96,2439.58 h25
  text "X" at 12507.97,2293.39 h25
  text "RoHS" at 12635.96,2293.39 h25
  text "OTHER" at 13280.36,2293.39 h25
  text "PER ORDER" at 13677.42,2293.39 h25
  text "ALL BOARDS MUST MEET OR EXCEED UL94-V0 REQUIREMENTS." at 11361,2139.57 h25
  text "PCB MUST BEAR THE UL94V-0 UL REGISTERED MATERIAL ID NUMBER" at 11361,2023.5 h25
  text "ADDITIONAL REQUIREMENTS:" at 11333.46,1854.08 h25
  text "MICROSECTION:" at 11408.23,1746.95 h25
  text "YES" at 12313.96,1746.95 h25
  text "REQUIRED" at 13175.46,1602.62 h25
  text "BARE BOARD ELEC. TEST:" at 11408.23,1599.76 h25
  text "NONE" at 12713.96,1599.76 h25
  text "X" at 13057.46,1599.76 h25
  text "PER ORDER" at 13767.46,1599.76 h25
  text "XX MIL VIAS REQUIRE NON-CONDUCTIVE FILL AND PLANARIZE" at 11576.38,1394.82 h25
  text "XX MIL VIAS REQUIRE CONDUCTIVE FILL AND PLANARIZE" at 11584.38,1290.84 h25
  text "OUTER XX MIL TRACES REQUIRE 50 OHM SINGLE-ENDED IMPEDANCE" at 11583.39,1127.46 h25
  text "LAYER 2 & 3 (INNER LAYERS) XX MIL WIDE, XX MIL SPACE / TRACES REQUIRE 100 OHM DIFFERENTIAL IMPEDANCE" at 11575.39,891.74 h25
  text ".Layer_Name" at 577,-858.49 h25
M11 Gerber Information:
  lines w10: -292,-930.17 6308,-930.17 ; -292,-726.83 6310,-726.83 ; -292,-523.5 -292,-1133.5 3713,-1133.5 6310,-1133.5 6310,-523.5 -291.5,-523.5 -291.5,-1133.5 1284,-1133.5 ; 2173,-1133.5 2173,-523.5 ; 3440,-726.83 3440,-523.5 ; 4280,-726.83 4280,-523.5 ; 4902,-1140 4902,-937.17
  text "ALL ARTWORK VIEWED FROM TOP SIDE" at -228.5,-655.67 h25
  text "BOARD #:" at 2248,-655.67 h25
  text ".PRJ_Number" at 2793.5,-655.67 h25
  text "REV:" at 3638,-655.67 h25
  text ".PCB_Rev" at 3929.5,-655.67 h25
  text "SVN REV:" at 4476,-655.67 h25
  text ".VersionControl_RevNumber" at 4982,-655.67 h25
  text "LAYER NAME =" at -228.5,-858.49 h25
  text "TID #:" at 2248,-859 h25
  text ".TID" at 2793.5,-859 h25
  text "PLOT NAME =" at -228.5,-1064.34 h25
  text ".plot_File_Name" at 577,-1064.34 h25
  text "GENERATED    :" at 2250,-1064.34 h25
  text ".Print_Date" at 3119.5,-1064.34 h25
  text ".Print_Time" at 3848.5,-1064.34 h25
  text "TEXAS INSTRUMENTS" at 5113,-1064.34 h25
M12 Stackup:
  drawing of 295 lines, arcs and shapes, not listed
  text "Layer" at 5769.38,1029.55 h60
  text "Name" at 6179.29,1029.55 h60
  text "Material" at 7119.03,1029.55 h60
  text "Thickness" at 7978.8,1029.55 h60
  text "Constant" at 8628.63,1029.55 h60
  text "Board Layer Stack" at 9198.5,1029.55 h60
  text "Top Overlay" at 6179.29,909.55 h60
  text "Top Solder" at 6179.29,789.55 h60
  text "Solder Resist" at 7119.03,789.55 h60
  text "0.40mil" at 7978.8,789.55 h60
  text "3.5" at 8628.63,789.55 h60
  text "1" at 5769.38,669.55 h60
  text "Top Layer" at 6179.29,669.55 h60
  text "2.80mil" at 7978.8,669.55 h60
  text "Dielectric 1" at 6179.29,549.55 h60
  text "FR4 370" at 7119.03,549.55 h60
  text "11.40mil" at 7978.8,549.55 h60
  text "4.2" at 8628.63,549.55 h60
  text "2" at 5769.38,429.55 h60
  text "Signal Layer 1" at 6179.29,429.55 h60
  text "1.40mil" at 7978.8,429.55 h60
  text "Dielectric 2" at 6179.29,309.55 h60
  text "FR4 370" at 7119.03,309.55 h60
  text "30.00mil" at 7978.8,309.55 h60
  text "4.2" at 8628.63,309.55 h60
  text "3" at 5769.38,189.55 h60
  text "Signal Layer 2" at 6179.29,189.55 h60
  text "1.40mil" at 7978.8,189.55 h60
  text "Dielectric 3" at 6179.29,69.55 h60
  text "FR4 370" at 7119.03,69.55 h60
  text "11.40mil" at 7978.8,69.55 h60
  text "4.2" at 8628.63,69.55 h60
  text "4" at 5769.38,-50.45 h60
  text "Bottom Layer" at 6179.29,-50.45 h60
  text "2.80mil" at 7978.8,-50.45 h60
  text "Bottom Solder" at 6179.29,-170.45 h60
  text "Solder Resist" at 7119.03,-170.45 h60
  text "0.40mil" at 7978.8,-170.45 h60
  text "3.5" at 8628.63,-170.45 h60
  text "Bottom Overlay" at 6179.29,-290.45 h60
  text ".Layer_Name" at 577,-858.49 h25
M13 Component Bodies Top:
  text ".Layer_Name" at 577,-858.49 h25
M14 Component Bodies Bottom:
  text ".Layer_Name" at 577,-858.49 h25
M15 Courtyards Top:
  text ".Layer_Name" at 577,-858.49 h25
M16 Courtyards Bottom:
  text ".Layer_Name" at 577,-858.49 h25
Drill Drawing:
  circle w10: c134.98,7580.15 r20
  circle w10: c134.98,7580.15 r33.33
  circle w10: c134.98,6380.15 r33.33
  lines w10: 101.65,5746.82 101.65,5763.49 118.32,5780.15 101.65,5796.82 101.65,5813.49 118.32,5813.49 134.98,5796.82 151.65,5813.49 168.32,5813.49 168.32,5796.82 151.65,5780.15 168.32,5763.49 168.32,5746.82 151.65,5746.82 134.98,5763.49 118.32,5746.82 101.65,5746.82 ; 101.65,5913.49 118.32,5913.49 134.98,5896.82 151.65,5913.49 168.32,5913.49 151.65,5930.15 168.32,5946.82 151.65,5946.82 134.98,5963.49 118.32,5946.82 101.65,5946.82 118.32,5930.15 101.65,5913.49 ; 101.65,6063.49 118.32,6063.49 118.32,6046.82 151.65,6046.82 151.65,6063.49 168.32,6063.49 168.32,6096.82 151.65,6096.82 151.65,6113.49 118.32,6113.49 118.32,6096.82 101.65,6096.82 101.65,6063.49 ; 101.65,6196.82 134.98,6213.49 168.32,6196.82 151.65,6230.15 168.32,6263.49 134.98,6246.82 101.65,6263.49 118.32,6230.15 101.65,6196.82 ; 101.65,6563.49 168.32,6563.49 134.98,6496.82 101.65,6563.49 ; 101.65,6713.49 168.32,6713.49 134.98,6646.82 101.65,6713.49 ; 101.65,6813.49 118.32,6813.49 134.98,6796.82 151.65,6813.49 168.32,6813.49 151.65,6830.15 168.32,6846.82 151.65,6846.82 134.98,6863.49 118.32,6846.82 101.65,6846.82 118.32,6830.15 101.65,6813.49 ; 101.65,6980.15 134.98,6946.82 168.32,6980.15 134.98,7013.49 101.65,6980.15 ; 101.65,7096.82 168.32,7096.82 168.32,7163.49 101.65,7163.49 101.65,7096.82 ; 101.65,7246.82 168.32,7246.82 168.32,7313.49 101.65,7313.49 101.65,7246.82 ; 101.65,7413.49 118.32,7413.49 118.32,7396.82 151.65,7396.82 151.65,7413.49 168.32,7413.49 168.32,7446.82 151.65,7446.82 151.65,7463.49 118.32,7463.49 118.32,7446.82 101.65,7446.82 101.65,7413.49 ; 114.98,6550.15 154.98,6550.15 134.98,6510.15 114.98,6550.15 ; 114.98,6820.15 124.98,6820.15 134.98,6810.15 144.98,6820.15 154.98,6820.15 144.98,6830.15 154.98,6840.15 144.98,6840.15 134.98,6850.15 124.98,6840.15 114.98,6840.15 124.98,6830.15 114.98,6820.15 ; 114.98,7110.15 154.98,7110.15 154.98,7150.15 114.98,7150.15 114.98,7110.15 ; 114.98,7420.15 124.98,7420.15 124.98,7410.15 144.98,7410.15 144.98,7420.15 154.98,7420.15 154.98,7440.15 144.98,7440.15 144.98,7450.15 124.98,7450.15 124.98,7440.15 114.98,7440.15 114.98,7420.15
  lines w12: 41.86,5701.82 6442.09,5701.82 ; 41.86,7651.82 6442.09,7651.82 ; 592.73,5551.82 592.73,7801.82 ; 1230.57,5551.82 1230.57,7801.82 ; 2576.17,5551.82 2576.17,7801.82 ; 3082.05,5551.82 3082.05,7801.82 ; 3815.85,5551.82 3815.85,7801.82 ; 5315.4,5551.82 5315.4,7801.82 ; 41.86,5551.82 6442.09,5551.82 6442.09,7801.82 41.86,7801.82 41.86,5551.82
  text "Symbol" at 131.86,7696.82 h72
  text "Quantity" at 637.73,7696.82 h72
  text "Finished Hole Size" at 1275.57,7696.82 h72
  text "Plated" at 2621.17,7696.82 h72
  text "Hole Type" at 3127.05,7696.82 h72
  text "Drill Layer Pair" at 3860.85,7696.82 h72
  text "Hole Tolerance" at 5360.4,7696.82 h72
  text "23" at 637.73,7546.82 h60
  text "7.87mil (0.200mm)" at 1275.57,7546.82 h60
  text "PTH" at 2621.17,7546.82 h60
  text "Round" at 3127.05,7546.82 h60
  text "Top Layer - Bottom Layer" at 3860.85,7546.82 h60
  text "4" at 637.73,7396.82 h60
  text "8.00mil (0.203mm)" at 1275.57,7396.82 h60
  text "PTH" at 2621.17,7396.82 h60
  text "Round" at 3127.05,7396.82 h60
  text "Top Layer - Bottom Layer" at 3860.85,7396.82 h60
  text "870" at 637.73,7246.82 h60
  text "13.78mil (0.350mm)" at 1275.57,7246.82 h60
  text "PTH" at 2621.17,7246.82 h60
  text "Round" at 3127.05,7246.82 h60
  text "Top Layer - Bottom Layer" at 3860.85,7246.82 h60
  text "1" at 637.73,7096.82 h60
  text "17.72mil (0.450mm)" at 1275.57,7096.82 h60
  text "PTH" at 2621.17,7096.82 h60
  text "Round" at 3127.05,7096.82 h60
  text "Top Layer - Bottom Layer" at 3860.85,7096.82 h60
  text "14" at 637.73,6946.82 h60
  text "40.00mil (1.016mm)" at 1275.57,6946.82 h60
  text "PTH" at 2621.17,6946.82 h60
  text "Round" at 3127.05,6946.82 h60
  text "Top Layer - Bottom Layer" at 3860.85,6946.82 h60
  text "24" at 637.73,6796.82 h60
  text "40.16mil (1.020mm)" at 1275.57,6796.82 h60
  text "PTH" at 2621.17,6796.82 h60
  text "Round" at 3127.05,6796.82 h60
  text "Top Layer - Bottom Layer" at 3860.85,6796.82 h60
  text "+/-3.15mil" at 5360.4,6796.82 h60
  text "6" at 637.73,6646.82 h60
  text "40.16mil (1.020mm)" at 1275.57,6646.82 h60
  text "PTH" at 2621.17,6646.82 h60
  text "Round" at 3127.05,6646.82 h60
  text "Top Layer - Bottom Layer" at 3860.85,6646.82 h60
  text "14" at 637.73,6496.82 h60
  text "43.31mil (1.100mm)" at 1275.57,6496.82 h60
  text "PTH" at 2621.17,6496.82 h60
  text "Round" at 3127.05,6496.82 h60
  text "Top Layer - Bottom Layer" at 3860.85,6496.82 h60
  text "+/-1.97mil" at 5360.4,6496.82 h60
  text "2" at 637.73,6346.82 h60
  text "51.18mil (1.300mm)" at 1275.57,6346.82 h60
  text "PTH" at 2621.17,6346.82 h60
  text "Round" at 3127.05,6346.82 h60
  text "Top Layer - Bottom Layer" at 3860.85,6346.82 h60
  text "4" at 637.73,6196.82 h60
  text "62.99mil (1.600mm)" at 1275.57,6196.82 h60
  text "PTH" at 2621.17,6196.82 h60
  text "Round" at 3127.05,6196.82 h60
  text "Top Layer - Bottom Layer" at 3860.85,6196.82 h60
  text "16" at 637.73,6046.82 h60
  text "62.99mil (1.600mm)" at 1275.57,6046.82 h60
  text "PTH" at 2621.17,6046.82 h60
  text "Round" at 3127.05,6046.82 h60
  text "Top Layer - Bottom Layer" at 3860.85,6046.82 h60
  text "+3.94mil/-0.00mil" at 5360.4,6046.82 h60
  text "12" at 637.73,5896.82 h60
  text "63.00mil (1.600mm)" at 1275.57,5896.82 h60
  text "PTH" at 2621.17,5896.82 h60
  text "Round" at 3127.05,5896.82 h60
  text "Top Layer - Bottom Layer" at 3860.85,5896.82 h60
  text "2" at 637.73,5746.82 h60
  text "23.62mil (0.600mm)" at 1275.57,5746.82 h60
  text "PTH" at 2621.17,5746.82 h60
  text "Slot" at 3127.05,5746.82 h60
  text "Top Layer - Bottom Layer" at 3860.85,5746.82 h60
  text "992 Total" at 637.73,5596.82 h60
  text "Slot definitions :" at 131.86,5451.85 h60
  text "Routed Path Length" at 1164.55,5451.85 h60
  text "= Calculated from tool start centre position to tool end centre position." at 2267.21,5451.85 h60
  text "Hole Length" at 1164.55,5351.87 h60
  text "= Routed Path Length + Tool Size = Slot length as defined in the PCB layout" at 1857.35,5351.87 h60
  text ".Layer_Name" at 577,-858.49 h25
Mechanical 17:
  text ".Layer_Name" at 577,-858.49 h25
Mechanical 18:
  text ".Layer_Name" at 577,-858.49 h25
Mechanical 19:
  text ".Layer_Name" at 577,-858.49 h25

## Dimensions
0,-400 to 1000,-400 on M2 Board Dimensions
0,0 to 0,4078.74 on M2 Board Dimensions
0,0 to 3224.41,0 on M2 Board Dimensions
